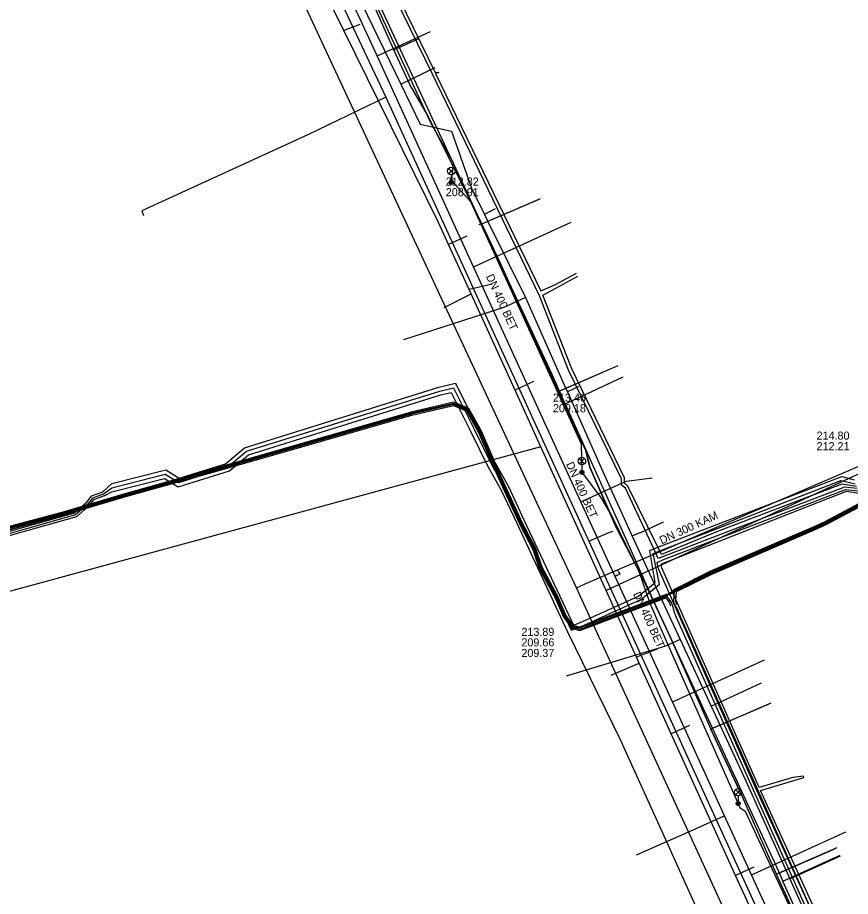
# Model space of a CAD drawing. Extents: x -595540 to -593988, y -1160850 to -1159202.
# Drawn here: x -595436.2 to -595353.5, y -1160327.6 to -1160240.3 of the extents above; entities that cross this region are included whole.
import ezdxf

# ---------------------------------------------------------------- set-up
doc = ezdxf.new("R2010")
doc.units = 0
for name, color, linetype in [('BVK-JEDNOTNA_popisy', 7, 'Continuous'), ('BVK-JEDNOTNA_trasa sítě', 7, 'Continuous'), ('BVK-VODOVOD_trasa sítě', 7, 'Continuous'), ('CETIN_kabel podzemní', 7, 'Continuous'), ('DESTOVA_trasa neprovozované sítě', 7, 'Continuous'), ('DSP-SDEL-VODAFONE_kabel', 7, 'Continuous'), ('EON-NN_kabel', 7, 'Continuous'), ('EON-SDEL_kabel', 7, 'Continuous'), ('EON-VN_kabel', 7, 'Continuous'), ('INNOGY-NTL_trasa sítě', 7, 'Continuous'), ('INNOGY-STL_trasa sítě', 7, 'Continuous'), ('JEDNOTNA_trasa neprovozované sítě', 7, 'Continuous'), ('TSB_kabel VO', 7, 'Continuous'), ('TSB_lampy VO', 7, 'Continuous')]:
    doc.layers.add(name, color=color, linetype=linetype)

msp = doc.modelspace()

# ---------------------------------------------------------------- linework, layer by layer
at = {"layer": 'BVK-JEDNOTNA_popisy'}
for p, q in [((-595393.674, -1160257.105), (-595393.674, -1160257.105)), ((-595383.033, -1160278.566), (-595383.033, -1160278.566)), ((-595356.854, -1160282.335), (-595356.854, -1160282.335)), ((-595386.166, -1160302.347), (-595386.166, -1160302.347))]:
    msp.add_line(p, q, dxfattribs=at)
at = {"layer": 'BVK-JEDNOTNA_trasa sítě'}
for p, q in [((-595377.75, -1160297.181), (-595384.22, -1160282.913)), ((-595352.476, -1160285.534), (-595377.75, -1160297.181))]:
    msp.add_line(p, q, dxfattribs=at)
for points in [[(-595394.408, -1160260.629), (-595403.797, -1160241.575), (-595403.797, -1160241.574), (-595405.519, -1160238.08), (-595405.641, -1160237.831), (-595408.341, -1160232.353), (-595408.632, -1160231.761), (-595411.711, -1160225.514)], [(-595384.22, -1160282.913), (-595386.795, -1160277.281), (-595391.156, -1160267.741), (-595391.364, -1160267.286), (-595393.406, -1160262.821), (-595394.408, -1160260.629)], [(-595384.22, -1160282.913), (-595480.942, -1160309.235), (-595481.701, -1160309.467)], [(-595361.285, -1160333.339), (-595364.893, -1160325.51), (-595371.286, -1160311.423), (-595374.469, -1160304.411), (-595374.738, -1160303.82), (-595374.738, -1160303.819), (-595377.75, -1160297.181)]]:
    msp.add_lwpolyline(points, dxfattribs=at)
at = {"layer": 'BVK-VODOVOD_trasa sítě'}
for p, q in [((-595380.702, -1160296.931), (-595431.86, -1160187.16)), ((-595376.685, -1160295.719), (-595376.865, -1160295.797)), ((-595376.606, -1160295.138), (-595376.474, -1160295.408)), ((-595380.702, -1160296.931), (-595379.837, -1160296.528)), ((-595328.79, -1160410.05), (-595380.702, -1160296.931))]:
    msp.add_line(p, q, dxfattribs=at)
for points in [[(-595376.865, -1160295.797), (-595380.252, -1160288.396), (-595390.923, -1160265.051), (-595400.501, -1160244.099), (-595402.567, -1160239.579), (-595403.377, -1160237.806)], [(-595400.501, -1160244.099), (-595399.947, -1160243.845), (-595395.196, -1160241.674)], [(-595376.606, -1160295.138), (-595340.47, -1160279.609), (-595318.965, -1160271.912), (-595313.72, -1160270.191), (-595290.11, -1160262.448), (-595279.893, -1160259.117)], [(-595390.923, -1160265.051), (-595390.688, -1160264.943), (-595381.233, -1160260.621)], [(-595380.252, -1160288.396), (-595376.132, -1160286.512), (-595375.716, -1160286.322), (-595373.173, -1160285.991)], [(-595379.837, -1160296.528), (-595377.076, -1160295.341), (-595376.606, -1160295.138)], [(-595336.907, -1160383.216), (-595337.17, -1160382.641), (-595337.421, -1160382.085), (-595338.083, -1160380.539), (-595339.67, -1160377.173), (-595340.408, -1160375.558), (-595342.432, -1160371.131), (-595343.583, -1160368.614), (-595345.447, -1160364.535), (-595348.862, -1160357.064), (-595354.128, -1160345.543), (-595354.407, -1160344.933), (-595363.32, -1160325.437), (-595366.003, -1160319.566), (-595371.17, -1160308.264), (-595371.537, -1160307.461), (-595376.865, -1160295.797)], [(-595376.474, -1160295.408), (-595376.39, -1160295.581), (-595376.685, -1160295.719)], [(-595371.17, -1160308.264), (-595370.94, -1160308.159), (-595362.019, -1160304.081)], [(-595366.003, -1160319.566), (-595366.141, -1160319.639), (-595369.444, -1160321.116), (-595374.761, -1160323.474)], [(-595363.32, -1160325.437), (-595363.091, -1160325.332), (-595353.936, -1160321.147)]]:
    msp.add_lwpolyline(points, dxfattribs=at)
at = {"layer": 'CETIN_kabel podzemní'}
for points in [[(-595383.11, -1160275.74), (-595395.03, -1160250.25), (-595406.39, -1160225.81), (-595411.44, -1160215.07)], [(-595398.83, -1160243.48), (-595401.19, -1160238.19)], [(-595398.83, -1160243.48), (-595396.42, -1160242.39)], [(-595390.09, -1160260.77), (-595395.46, -1160250.01), (-595397.23, -1160246.94), (-595398.83, -1160243.48)], [(-595390.09, -1160260.77), (-595384.27, -1160258.25)], [(-595390.09, -1160260.77), (-595390.39, -1160260.88)], [(-595382.47, -1160277.43), (-595383.72, -1160274.69), (-595386.32, -1160269), (-595388.28, -1160264.63), (-595390.09, -1160260.77)], [(-595376.59, -1160274.87), (-595382.47, -1160277.43)], [(-595382.02, -1160278.21), (-595383.11, -1160275.74)], [(-595381.09, -1160278.33), (-595376.07, -1160275.98)], [(-595380.6, -1160281.48), (-595382.47, -1160277.43)], [(-595381.82, -1160278.67), (-595382.02, -1160278.21)], [(-595381.82, -1160278.67), (-595381.09, -1160278.33)], [(-595381.82, -1160278.67), (-595375.82, -1160291.98)], [(-595380.6, -1160281.48), (-595379.77, -1160283.29), (-595379.37, -1160284.96), (-595376.63, -1160291.17), (-595373.94, -1160296.34), (-595371.35, -1160301.86), (-595367.35, -1160310.95)], [(-595375.82, -1160291.98), (-595373.15, -1160298.01)], [(-595373.15, -1160298.01), (-595360.81, -1160324.7)], [(-595361.39, -1160308.39), (-595367.35, -1160310.95)], [(-595364.79, -1160316.43), (-595367.35, -1160310.95)], [(-595360.84, -1160325.38), (-595363.18, -1160320.05), (-595364.34, -1160317.38), (-595364.79, -1160316.43)], [(-595354.84, -1160322.75), (-595360.84, -1160325.38)], [(-595360.19, -1160326.06), (-595354.51, -1160323.47)], [(-595360.81, -1160324.7), (-595360.19, -1160326.06)], [(-595353, -1160342.6), (-595354.65, -1160338.99), (-595355.95, -1160336.11), (-595360.84, -1160325.38)], [(-595349.26, -1160350.3), (-595360.19, -1160326.06)]]:
    msp.add_lwpolyline(points, dxfattribs=at)
at = {"layer": 'DESTOVA_trasa neprovozované sítě'}
for p, q in [((-595389.08, -1160266.77), (-595391.364, -1160267.286)), ((-595393.84, -1160269.08), (-595391.156, -1160267.741)), ((-595372.69, -1160303.01), (-595374.738, -1160303.819)), ((-595377.25, -1160305.6), (-595374.469, -1160304.411))]:
    msp.add_line(p, q, dxfattribs=at)
at = {"layer": 'DSP-SDEL-VODAFONE_kabel'}
for p, q in [((-595398.83, -1160243.48), (-595396.418, -1160242.391)), ((-595395.458, -1160250.01), (-595397.228, -1160246.939)), ((-595390.09, -1160260.775), (-595384.483, -1160258.345)), ((-595386.324, -1160268.998), (-595388.284, -1160264.63)), ((-595382.472, -1160277.425), (-595376.786, -1160274.949)), ((-595373.94, -1160296.341), (-595376.634, -1160291.167)), ((-595367.346, -1160310.945), (-595361.615, -1160308.481)), ((-595360.844, -1160325.382), (-595355.044, -1160322.843))]:
    msp.add_line(p, q, dxfattribs=at)
for points in [[(-595397.228, -1160246.939), (-595398.83, -1160243.48), (-595401.188, -1160238.19), (-595399.22, -1160236.653)], [(-595355.952, -1160336.113), (-595360.844, -1160325.382), (-595364.342, -1160317.383), (-595367.346, -1160310.945), (-595371.348, -1160301.864), (-595373.94, -1160296.341), (-595376.634, -1160291.167), (-595379.368, -1160284.956), (-595379.771, -1160283.287), (-595382.472, -1160277.425), (-595383.721, -1160274.693), (-595386.324, -1160268.998), (-595388.284, -1160264.63), (-595390.09, -1160260.775), (-595395.458, -1160250.01), (-595397.228, -1160246.939), (-595398.83, -1160243.48), (-595401.188, -1160238.19)], [(-595388.284, -1160264.63), (-595390.09, -1160260.775), (-595395.458, -1160250.01)], [(-595383.721, -1160274.693), (-595386.324, -1160268.998)], [(-595376.675, -1160291.075), (-595379.368, -1160284.956), (-595379.771, -1160283.287), (-595382.472, -1160277.425), (-595383.721, -1160274.693)], [(-595363.177, -1160320.046), (-595364.342, -1160317.383), (-595367.346, -1160310.945), (-595371.348, -1160301.864), (-595373.94, -1160296.341)], [(-595354.647, -1160338.991), (-595355.952, -1160336.113), (-595360.844, -1160325.382), (-595363.177, -1160320.046)]]:
    msp.add_lwpolyline(points, dxfattribs=at)
at = {"layer": 'EON-NN_kabel'}
for points in [[(-595352.822, -1160287.069), (-595354.069, -1160286.924), (-595366.398, -1160291.637), (-595372.59, -1160294.011), (-595372.859, -1160293.429), (-595373.029, -1160293.062), (-595375.818, -1160287.028), (-595376.237, -1160286.731), (-595376.219, -1160286.102), (-595381.473, -1160275.313), (-595384.354, -1160267.93), (-595395, -1160245.915), (-595400.776, -1160234.032), (-595408.651, -1160218.022), (-595411.146, -1160212.845), (-595415.985, -1160202.938), (-595419.473, -1160195.718), (-595421.23, -1160195.244), (-595421.912, -1160195.506), (-595428.428, -1160198.738), (-595429.476, -1160199.28), (-595433.943, -1160198.058), (-595434.729, -1160197.953), (-595435.022, -1160198.153)], [(-595400.478, -1160233.939), (-595394.74, -1160245.742), (-595394.35, -1160245.749), (-595394.685, -1160245.849), (-595384.232, -1160267.441), (-595382.834, -1160266.847), (-595380.708, -1160265.686)], [(-595352.898, -1160286.879), (-595354.349, -1160286.626), (-595366.527, -1160291.275), (-595372.254, -1160293.623), (-595372.431, -1160293.263), (-595372.609, -1160292.901), (-595375.59, -1160286.836), (-595375.94, -1160286.539), (-595375.922, -1160285.997), (-595381.141, -1160275.19), (-595384.032, -1160267.85), (-595382.73, -1160267.182), (-595380.562, -1160265.984)], [(-595427.748, -1160287.432), (-595426.823, -1160286.576), (-595421.488, -1160285.211), (-595420.142, -1160286.029), (-595415.553, -1160284.602), (-595413.653, -1160283.014), (-595394.366, -1160276.998), (-595392.697, -1160276.616), (-595390.48, -1160281.074), (-595388.783, -1160284.503), (-595387.455, -1160286.86), (-595385.908, -1160290.18), (-595381.001, -1160300.624), (-595380.392, -1160300.407), (-595374.533, -1160297.748), (-595372.892, -1160296.384), (-595373.401, -1160293.206), (-595373.029, -1160293.062), (-595372.609, -1160292.901), (-595354.342, -1160285.86), (-595353.104, -1160286.214)], [(-595427.68, -1160287.62), (-595426.847, -1160286.995), (-595421.552, -1160285.64), (-595420.196, -1160286.465), (-595415.358, -1160284.96), (-595413.458, -1160283.372), (-595394.262, -1160277.384), (-595392.915, -1160277.076), (-595390.838, -1160281.252), (-595389.137, -1160284.69), (-595387.811, -1160287.043), (-595386.27, -1160290.35), (-595381.209, -1160301.123), (-595380.242, -1160300.778), (-595374.319, -1160298.09), (-595372.466, -1160296.551), (-595373.067, -1160293.51), (-595372.859, -1160293.429), (-595372.431, -1160293.263), (-595354.433, -1160286.285), (-595353.029, -1160286.607)], [(-595427.612, -1160287.808), (-595426.82, -1160287.4), (-595421.616, -1160286.069), (-595420.25, -1160286.901), (-595415.163, -1160285.318), (-595413.263, -1160283.73), (-595394.158, -1160277.77), (-595393.133, -1160277.536), (-595391.196, -1160281.43), (-595389.491, -1160284.877), (-595388.167, -1160287.226), (-595386.632, -1160290.52), (-595381.574, -1160301.288), (-595376.354, -1160312.006), (-595371.535, -1160322.638), (-595369.063, -1160328.096), (-595364.592, -1160338.188), (-595363.088, -1160341.376), (-595358.266, -1160352.281), (-595360.189, -1160353.241)], [(-595352.959, -1160338.606), (-595362.774, -1160317.063), (-595372.552, -1160295.047), (-595372.667, -1160294.423), (-595372.125, -1160294.14), (-595353.978, -1160287.15), (-595352.699, -1160287.29)], [(-595427.748, -1160287.432), (-595428.88, -1160287.841), (-595429.505, -1160288.611), (-595430.528, -1160289.51), (-595435.504, -1160290.918), (-595441.522, -1160292.621), (-595442.86, -1160292.679), (-595444.385, -1160292.452), (-595447.063, -1160292.18), (-595448.967, -1160292.238), (-595449.046, -1160292.24)], [(-595427.68, -1160287.62), (-595428.76, -1160288.01), (-595429.36, -1160288.75), (-595430.43, -1160289.69), (-595435.45, -1160291.11), (-595441.49, -1160292.82), (-595442.87, -1160292.88), (-595444.41, -1160292.65), (-595447.07, -1160292.38), (-595449.04, -1160292.44)], [(-595427.612, -1160287.808), (-595428.64, -1160288.179), (-595429.215, -1160288.889), (-595430.332, -1160289.87), (-595435.396, -1160291.302), (-595441.458, -1160293.019), (-595442.881, -1160293.081), (-595444.435, -1160292.848), (-595447.077, -1160292.58), (-595449.034, -1160292.64)], [(-595352.674, -1160338.373), (-595362.428, -1160317.069), (-595358.116, -1160315.778), (-595358.167, -1160315.631), (-595359.198, -1160315.755), (-595362.551, -1160316.763), (-595372.239, -1160294.871), (-595372.254, -1160294.552), (-595371.661, -1160294.32), (-595353.87, -1160287.322), (-595352.647, -1160287.513), (-595352.587, -1160287.522)]]:
    msp.add_lwpolyline(points, dxfattribs=at)
at = {"layer": 'EON-SDEL_kabel'}
for points in [[(-595370.764, -1160298.591), (-595370.825, -1160298.18), (-595370.766, -1160297.302), (-595367.336, -1160295.591), (-595357.058, -1160291.173), (-595355.911, -1160290.639), (-595352.013, -1160288.571), (-595348.249, -1160287.874), (-595341.253, -1160285.435), (-595335.765, -1160282.776), (-595328.421, -1160278.44), (-595326.973, -1160277.851), (-595325.658, -1160277.879), (-595324.139, -1160278.809), (-595322.83, -1160280.632), (-595322.031, -1160283.011), (-595322.091, -1160285.971), (-595320.854, -1160288.139)], [(-595352.08, -1160288.38), (-595356, -1160290.46), (-595357.14, -1160290.99), (-595367.42, -1160295.41), (-595370.933, -1160297.162), (-595371.186, -1160297.443), (-595371.455, -1160297.617), (-595371.755, -1160297.692), (-595380.38, -1160300.95), (-595381.02, -1160300.78), (-595381.8, -1160299.75), (-595382.64, -1160297.83), (-595384.21, -1160294.92), (-595384.83, -1160293.05), (-595386.12, -1160290.63), (-595388.25, -1160285.95), (-595390.23, -1160281.41), (-595391.47, -1160279.2), (-595392.89, -1160278.61), (-595397.1, -1160279.57), (-595403.66, -1160281.46), (-595410.22, -1160283.36), (-595417.87, -1160285.55), (-595425.5, -1160287.68), (-595431.54, -1160289.47), (-595437.23, -1160291.01)], [(-595437.178, -1160291.203), (-595431.485, -1160289.662), (-595425.445, -1160287.872), (-595417.816, -1160285.742), (-595410.165, -1160283.552), (-595403.604, -1160281.652), (-595397.05, -1160279.764), (-595392.908, -1160278.819), (-595391.611, -1160279.358), (-595390.409, -1160281.499), (-595388.433, -1160286.031), (-595386.299, -1160290.719), (-595385.015, -1160293.129), (-595384.394, -1160295), (-595382.82, -1160297.918), (-595381.974, -1160299.852), (-595381.138, -1160300.956), (-595380.369, -1160301.16), (-595371.82, -1160297.93), (-595371.46, -1160298.43), (-595371.345, -1160298.731)]]:
    msp.add_lwpolyline(points, dxfattribs=at)
at = {"layer": 'EON-VN_kabel'}
for points in [[(-595370.962, -1160298.62), (-595371.026, -1160298.188), (-595370.959, -1160297.286), (-595367.378, -1160295.501), (-595357.099, -1160291.081), (-595355.956, -1160290.55), (-595352.047, -1160288.476), (-595348.274, -1160287.777), (-595341.292, -1160285.343), (-595335.813, -1160282.688), (-595328.466, -1160278.35), (-595326.991, -1160277.75), (-595325.629, -1160277.779), (-595324.069, -1160278.735), (-595322.74, -1160280.586), (-595321.93, -1160282.995), (-595321.99, -1160285.946), (-595320.767, -1160288.09)], [(-595352.113, -1160288.284), (-595356.045, -1160290.37), (-595357.181, -1160290.899), (-595367.462, -1160295.319), (-595370.995, -1160297.081), (-595371.251, -1160297.366), (-595371.495, -1160297.525), (-595371.785, -1160297.596), (-595380.385, -1160300.845), (-595380.961, -1160300.692), (-595381.713, -1160299.699), (-595382.55, -1160297.786), (-595384.118, -1160294.88), (-595384.738, -1160293.01), (-595386.03, -1160290.586), (-595388.159, -1160285.909), (-595390.14, -1160281.365), (-595391.4, -1160279.121), (-595392.881, -1160278.505), (-595397.125, -1160279.473), (-595403.688, -1160281.364), (-595410.248, -1160283.264), (-595417.897, -1160285.454), (-595425.528, -1160287.584), (-595431.567, -1160289.374), (-595437.256, -1160290.914)], [(-595371.158, -1160298.66), (-595371.282, -1160298.334), (-595371.689, -1160297.774), (-595380.375, -1160301.055), (-595381.079, -1160300.868), (-595381.887, -1160299.801), (-595382.73, -1160297.874), (-595384.302, -1160294.96), (-595384.922, -1160293.09), (-595386.21, -1160290.674), (-595388.341, -1160285.991), (-595390.32, -1160281.455), (-595391.54, -1160279.279), (-595392.899, -1160278.715), (-595397.075, -1160279.667), (-595403.632, -1160281.556), (-595410.192, -1160283.456), (-595417.843, -1160285.646), (-595425.472, -1160287.776), (-595431.513, -1160289.566), (-595437.204, -1160291.107)], [(-595280.437, -1160465.869), (-595293.222, -1160447.996), (-595303.033, -1160434.066), (-595304.576, -1160432.929), (-595310.638, -1160424.467), (-595312.852, -1160421.521), (-595315.519, -1160417.675), (-595317.564, -1160414.9), (-595321.47, -1160409.102), (-595325.437, -1160401.41), (-595327.592, -1160395.996), (-595328.92, -1160393.313), (-595338.948, -1160370.998), (-595340.39, -1160367.57), (-595342.93, -1160361.937), (-595346.058, -1160355.266), (-595351.584, -1160342.645), (-595353.202, -1160339.276), (-595370.77, -1160299.882), (-595370.959, -1160299.379), (-595371.158, -1160298.66)], [(-595370.962, -1160298.62), (-595370.587, -1160299.239), (-595370.397, -1160299.751), (-595352.837, -1160339.129)]]:
    msp.add_lwpolyline(points, dxfattribs=at)
at = {"layer": 'INNOGY-NTL_trasa sítě'}
for points in [[(-595403.15, -1160236.59), (-595398.15, -1160246.92), (-595396.23, -1160250.88), (-595393.11, -1160251.59), (-595391.12, -1160257.25), (-595389.83, -1160259.861), (-595389.49, -1160260.55), (-595385.76, -1160268.11), (-595381.64, -1160277.36), (-595381.598, -1160277.455), (-595377.97, -1160285.61), (-595375.46, -1160291.14), (-595375.156, -1160291.793), (-595370.39, -1160302.05), (-595367.31, -1160308.69), (-595363.87, -1160316.1), (-595359.5, -1160325.82), (-595352.09, -1160342.34)], [(-595398.15, -1160246.92), (-595394.73, -1160245.26)], [(-595388.763, -1160259.297), (-595389.83, -1160259.861)], [(-595385.76, -1160268.11), (-595387.92, -1160269.08), (-595397.87, -1160272.3), (-595397.88, -1160272.31)], [(-595380.476, -1160276.93), (-595381.598, -1160277.455)], [(-595372.074, -1160290.417), (-595374.277, -1160291.436), (-595374.654, -1160291.568), (-595374.811, -1160291.635), (-595375.156, -1160291.793)], [(-595370.39, -1160302.05), (-595371.84, -1160302.71), (-595381.71, -1160305.71)], [(-595367.31, -1160308.69), (-595362.31, -1160306.37)], [(-595359.5, -1160325.82), (-595354.47, -1160323.56)]]:
    msp.add_lwpolyline(points, dxfattribs=at)
at = {"layer": 'INNOGY-STL_trasa sítě'}
for points in [[(-595428.61, -1160186.86), (-595427.102, -1160189.809), (-595426.677, -1160190.675), (-595426.272, -1160191.572), (-595399.64, -1160248.2), (-595379.47, -1160292.3), (-595352.76, -1160350.74), (-595343.87, -1160370.55), (-595343.73, -1160370.85), (-595343.6, -1160371.12), (-595337.21, -1160384.65), (-595333.046, -1160394.737), (-595332.279, -1160396.328)], [(-595399.64, -1160248.2), (-595407.29, -1160251.91), (-595423.84, -1160259.47), (-595423.7, -1160259.95)], [(-595379.47, -1160292.3), (-595377.392, -1160291.397), (-595377.042, -1160291.29)]]:
    msp.add_lwpolyline(points, dxfattribs=at)
at = {"layer": 'JEDNOTNA_trasa neprovozované sítě'}
for p, q in [((-595402.198, -1160240.984), (-595403.797, -1160241.574)), ((-595391.587, -1160261.989), (-595393.406, -1160262.821)), ((-595384.976, -1160276.449), (-595386.795, -1160277.281)), ((-595369.465, -1160310.596), (-595371.286, -1160311.423)), ((-595363.072, -1160324.683), (-595364.893, -1160325.51))]:
    msp.add_line(p, q, dxfattribs=at)
at = {"layer": 'TSB_kabel VO'}
msp.add_lwpolyline([(-595400.48, -1160239.27), (-595395.16, -1160250.78), (-595392.94, -1160254.69), (-595393.11, -1160256.46), (-595391.22, -1160258.56), (-595380.24, -1160282.62), (-595380.16, -1160285.44), (-595378.26, -1160288.02), (-595377.16, -1160289.88), (-595374.47, -1160295.36), (-595373.45, -1160298.34), (-595372.3, -1160301.08), (-595364.46, -1160318.75), (-595363.96, -1160319.12), (-595355.99, -1160336.2)], dxfattribs=at)
at = {"layer": 'TSB_lampy VO'}
for p, q in [((-595393.395, -1160255.8), (-595392.865, -1160255.27)), ((-595393.395, -1160255.27), (-595392.865, -1160255.8)), ((-595393.395, -1160255.8), (-595392.865, -1160255.27)), ((-595393.395, -1160255.27), (-595392.865, -1160255.8)), ((-595393.13, -1160255.91), (-595393.13, -1160256.66)), ((-595393.13, -1160255.91), (-595393.13, -1160256.66)), ((-595380.425, -1160284.6), (-595379.895, -1160284.07)), ((-595380.425, -1160284.07), (-595379.895, -1160284.6)), ((-595380.425, -1160284.6), (-595379.895, -1160284.07)), ((-595380.425, -1160284.07), (-595379.895, -1160284.6)), ((-595380.16, -1160284.71), (-595380.16, -1160285.46)), ((-595380.16, -1160284.71), (-595380.16, -1160285.46)), ((-595364.905, -1160317.49), (-595364.375, -1160316.96)), ((-595364.905, -1160316.96), (-595364.375, -1160317.49)), ((-595364.905, -1160317.49), (-595364.375, -1160316.96)), ((-595364.905, -1160316.96), (-595364.375, -1160317.49)), ((-595364.64, -1160317.6), (-595364.64, -1160318.35)), ((-595364.64, -1160317.6), (-595364.64, -1160318.35))]:
    msp.add_line(p, q, dxfattribs=at)
for centre, radius in [((-595393.13, -1160255.535), 0.375), ((-595393.13, -1160255.535), 0.375), ((-595393.13, -1160256.66), 0.2), ((-595393.13, -1160256.66), 0.2), ((-595393.13, -1160256.66), 0.145), ((-595393.13, -1160256.66), 0.145), ((-595393.13, -1160256.66), 0.0876), ((-595393.13, -1160256.66), 0.0876), ((-595380.16, -1160284.335), 0.375), ((-595380.16, -1160284.335), 0.375), ((-595380.16, -1160285.46), 0.2), ((-595380.16, -1160285.46), 0.2), ((-595380.16, -1160285.46), 0.145), ((-595380.16, -1160285.46), 0.145), ((-595380.16, -1160285.46), 0.0876), ((-595380.16, -1160285.46), 0.0876), ((-595364.64, -1160317.225), 0.375), ((-595364.64, -1160317.225), 0.375), ((-595364.64, -1160318.35), 0.2), ((-595364.64, -1160318.35), 0.2), ((-595364.64, -1160318.35), 0.145), ((-595364.64, -1160318.35), 0.145), ((-595364.64, -1160318.35), 0.0876), ((-595364.64, -1160318.35), 0.0876)]:
    msp.add_circle(centre, radius, dxfattribs=at)

# ---------------------------------------------------------------- texts
at = {"layer": 'BVK-JEDNOTNA_popisy'}
for s, p in [('212.82', (-595393.674, -1160256.98)), ('208.91', (-595393.674, -1160258.03)), ('213.46', (-595383.033, -1160278.441)), ('209.18', (-595383.033, -1160279.491)), ('214.80', (-595356.854, -1160282.21)), ('212.21', (-595356.854, -1160283.26)), ('213.89', (-595386.166, -1160301.697)), ('209.66', (-595386.166, -1160302.747)), ('209.37', (-595386.166, -1160303.797))]:
    msp.add_text(s, height=0.8, dxfattribs=at).set_placement(p)
for s, rotation, p in [('DN 400 BET', 294.59098, (-595389.709, -1160265.995)), ('DN 400 BET', 294.39495, (-595381.76, -1160284.635)), ('DN 300 KAM', 24.75656, (-595372.228, -1160292.624)), ('DN 400 BET', 294.39229, (-595375.098, -1160297.537))]:
    msp.add_text(s, height=0.8, rotation=rotation, dxfattribs=at).set_placement(p)

doc.saveas('drawing.dxf')
